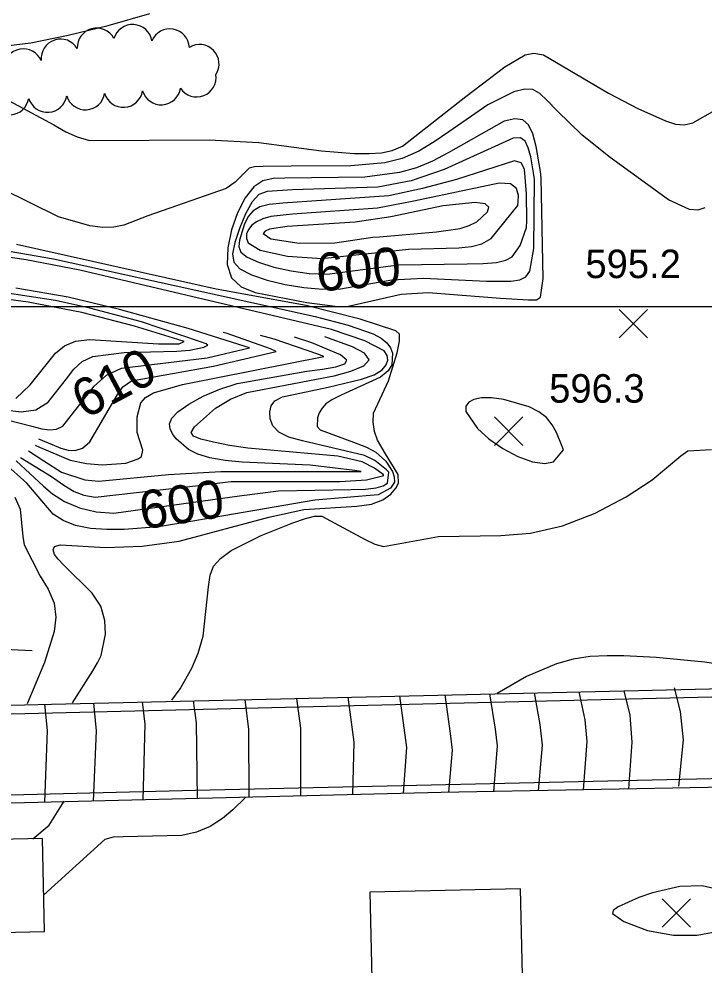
# Model space of a CAD drawing. Extents: x 79600 to 91800, y 75600 to 84400.
# Drawn here: x 88162.1 to 88522.6, y 78653.8 to 79151.4 of the extents above; entities that cross this region are included whole.
import ezdxf

# ---------------------------------------------------------------- set-up
doc = ezdxf.new("R2010")
doc.units = 0
for name, color, linetype in [('080-090$0$BLDG', 7, 'Continuous'), ('080-090$0$BRIDGE', 7, 'Continuous'), ('080-090$0$DRIVWY', 7, 'Continuous'), ('080-090$0$GRID', 7, 'Continuous'), ('080-090$0$INDEX', 7, 'Continuous'), ('080-090$0$INDXLBL', 7, 'Continuous'), ('080-090$0$INTER', 7, 'Continuous'), ('080-090$0$ROAD', 7, 'Continuous'), ('080-090$0$SPOTMARK', 7, 'Continuous'), ('080-090$0$SPOTS', 7, 'Continuous'), ('080-090$0$TREES', 7, 'Continuous')]:
    doc.layers.add(name, color=color, linetype=linetype)

# ---------------------------------------------------------------- blocks, each defined once
blk = doc.blocks.new('080-090$0$SPOTS')
at = {"layer": '080-090$0$SPOTMARK'}
for p, q in [((-0.5, -0.5), (0.5, 0.5)), ((-0.5, 0.5), (0.5, -0.5))]:
    blk.add_line(p, q, dxfattribs=at)

msp = doc.modelspace()

# ---------------------------------------------------------------- linework, layer by layer
at = {"layer": '080-090$0$BLDG'}
for points in [[(88098.7, 78669.76), (88175.62, 78671.53), (88174.5, 78720.41), (88097.58, 78718.64)], [(88346.79, 78692.15), (88354.12, 78373.51), (88433.35, 78375.34), (88426.02, 78693.98)]]:
    msp.add_lwpolyline(points, close=True, dxfattribs=at)
at = {"layer": '080-090$0$BRIDGE'}
for p, q in [((88179.19, 78791.07), (88533.01, 78799.31)), ((87904.96, 78784.84), (88179.19, 78791.07)), ((88825.9, 78753.07), (88384.29, 78744.54)), ((88384.29, 78744.54), (87934.81, 78733.66))]:
    msp.add_line(p, q, dxfattribs=at)
at = {"layer": '080-090$0$DRIVWY'}
msp.add_line((88131.98, 78821.14), (88169.06, 78819.2), dxfattribs=at)
at = {"layer": '080-090$0$GRID'}
msp.add_line((90000, 79000), (85000, 79000), dxfattribs=at)
at = {"layer": '080-090$0$INDEX'}
for points in [[(88429.23, 79045.27), (88429.2, 79059.44), (88428.16, 79072.45), (88426.37, 79075.74), (88422.83, 79076.74), (88392.28, 79067), (88374.37, 79062.17), (88356.66, 79058.27), (88300.88, 79054.58), (88293.83, 79053.79), (88288.77, 79052.51), (88285.3, 79050.54), (88282.82, 79047.62), (88280.81, 79043.69), (88278.19, 79035.08), (88277.83, 79031.61), (88278.88, 79028.7), (88282.13, 79026.04), (88288.13, 79023.39), (88296.18, 79020.92), (88305.34, 79018.91), (88314.79, 79017.6), (88324.3, 79017.11), (88361.82, 79022.12), (88397.96, 79022.59), (88406.34, 79022.71), (88413.28, 79023.27), (88418.22, 79024.45), (88421.57, 79026.31), (88425.86, 79032.18), (88429.18, 79041.68)], [(88528.32, 78693.96), (88521.58, 78695.48), (88509.88, 78695.15), (88495.38, 78691.78), (88488.28, 78689.33), (88477.36, 78684.43), (88474.73, 78682.6), (88474.32, 78680.96), (88480.33, 78676.77), (88492.71, 78672.04), (88506.4, 78669.6), (88518.98, 78669.58), (88529.21, 78671.43), (88536.38, 78674.68), (88538.7, 78676.63), (88540.1, 78678.72), (88540.44, 78681.01), (88537.33, 78686.56), (88529.83, 78693.45)]]:
    msp.add_lwpolyline(points, close=True, dxfattribs=at)
for points in [[(88160.67, 78919), (88175.05, 78905.62), (88179.7, 78901.62), (88186.08, 78897.69), (88193.94, 78894.33), (88202.77, 78892.13), (88212.09, 78891.5), (88279.42, 78900.85), (88298.67, 78903.19), (88336.86, 78903.94), (88344.43, 78904.15), (88350.02, 78904.81), (88353.78, 78905.89), (88356.02, 78907.3), (88356.72, 78913.08), (88355.5, 78914.29), (88349.36, 78919.11), (88343.91, 78921.84), (88311.37, 78929.55), (88304.18, 78931.46), (88298.78, 78933.99), (88295.63, 78937.34), (88294.31, 78941.12), (88294.18, 78944.81), (88294.83, 78947.96), (88296.77, 78950.56), (88300.76, 78952.7), (88324.84, 78957.8), (88342.37, 78961.9), (88348.94, 78964.28), (88353.16, 78966.83), (88355.37, 78969.43), (88356.16, 78971.97), (88355.9, 78974.37), (88354.17, 78976.76), (88344, 78982.15), (88326.57, 78988.06), (88222.38, 79012.53), (88194.15, 79019.26), (88165.83, 79024.73), (88146.62, 79027.59)], [(88135.26, 78945.74), (88168.84, 78937.21), (88174.22, 78935.77), (88178.39, 78935.25), (88181.9, 78935.72), (88185.22, 78937.28), (88201.71, 78958.21), (88208.15, 78964.08), (88216.12, 78967.74), (88261.13, 78973.18), (88283.38, 78978.34), (88280.66, 78979.34), (88251.17, 78988.63), (88214.96, 78998.5), (88187.92, 79005.01), (88160.5, 79009.79)], [(88480.35, 78798.08), (88483.45, 78785.18), (88484.59, 78771.1), (88482.76, 78746.44)], [(88362.33, 78795.34), (88366.05, 78768.29), (88364.3, 78744.05)], [(88226.95, 78792.18), (88228.3, 78780.44), (88227.31, 78740.74)]]:
    msp.add_lwpolyline(points, dxfattribs=at)
at = {"layer": '080-090$0$INTER'}
for points in [[(88142.81, 79115.89), (88180.37, 79095.72), (88186.72, 79092.08), (88192.78, 79089.3), (88199.26, 79087.52), (88262.16, 79087.89), (88288.35, 79086.47), (88321.21, 79082.02), (88338.51, 79080.67), (88346.3, 79080.54), (88352.78, 79080.93), (88358.42, 79082.15), (88363.9, 79084.54), (88397.21, 79110.63), (88417.79, 79126.28), (88428.35, 79132.44), (88432.96, 79133.39), (88438.05, 79132.5), (88472.22, 79112.38), (88487.66, 79104.32), (88502.29, 79097.74), (88507.61, 79096.01), (88512.09, 79095.65), (88516.7, 79096.81), (88528.35, 79103.45)], [(88522.87, 79052.03), (88519.29, 79050.83), (88514.96, 79051.14), (88503.77, 79056.17), (88473.19, 79078.43), (88458.35, 79090.24), (88445.2, 79103.12), (88440.08, 79108.48), (88436.11, 79112.25), (88432.49, 79114.26), (88428.19, 79114.49), (88422.48, 79112.97), (88408.78, 79106.22), (88388.25, 79091.96), (88380.63, 79086.71), (88372.42, 79081.85), (88363.68, 79078.04), (88354.54, 79075.7), (88336.78, 79074.08), (88305.37, 79073.91), (88290.59, 79073.83), (88286.06, 79073.6), (88283.16, 79072.88), (88275.86, 79065.47), (88271.17, 79062.23), (88229.95, 79047.92), (88217.21, 79043.01), (88211.99, 79041.8), (88206.28, 79041.63), (88199.33, 79042.58), (88182.96, 79047.33), (88031.53, 79121.93)], [(88190.35, 78791.8), (88200.89, 78808.62), (88203.42, 78812.73), (88205.36, 78816.7), (88207.62, 78827.79), (88207.3, 78835.07), (88205.11, 78842.53), (88200.68, 78849.45), (88185.49, 78864.39), (88182.67, 78867.35), (88180.89, 78869.83), (88180.06, 78872.11), (88180.82, 78873.92), (88183.99, 78874.86), (88207.67, 78873.44), (88226.97, 78874.13), (88246.46, 78876.71), (88293.58, 78889.36), (88312.05, 78893.38), (88339.8, 78895.18), (88347.52, 78896.25), (88353.5, 78898.51), (88357.74, 78901.53), (88360.42, 78904.65), (88361.72, 78907.33), (88361.59, 78911.81), (88354.92, 78922.62), (88350.77, 78929.87), (88349.14, 78934.49), (88348.4, 78939.31), (88348.58, 78944), (88356.58, 78961.12), (88361.16, 78975.73), (88362.34, 78981.95), (88362.24, 78985.55), (88360.41, 78987.37), (88341.56, 78993.45), (88313.24, 79000.65), (88265.78, 79009.23), (88160.83, 79032.77)], [(88152.9, 79029.95), (88180.36, 79025.29), (88291.82, 79000.77), (88317.97, 78994.94), (88335.31, 78990.32), (88348.41, 78985.72), (88352.63, 78983.47), (88355.59, 78981.07), (88357.52, 78978.43), (88358.57, 78975.58), (88358.29, 78969.5), (88356.35, 78966.33), (88352.33, 78963.05), (88331.6, 78953.51), (88326.74, 78951.11), (88323.62, 78948.98), (88321.59, 78946.76), (88320.14, 78944.22), (88319.17, 78941.57), (88318.94, 78937.09), (88320.51, 78935.28), (88338.03, 78928.76), (88344.93, 78926.2), (88349.85, 78923.63), (88355.11, 78918.88), (88358.57, 78913.45), (88359.52, 78910.53), (88359.69, 78907.79), (88357.64, 78904.71), (88351.08, 78901.12), (88317.69, 78898.34), (88253.52, 78887.34), (88235.58, 78884.33), (88217.41, 78882.9), (88208.35, 78882.86), (88199.7, 78883.5), (88191.94, 78885.05), (88185.42, 78887.66), (88180.16, 78891.04), (88166.29, 78907.28), (88154.48, 78917.7)], [(88154.48, 78945.82), (88163.24, 78944.83), (88171, 78945.9), (88177.44, 78949.92), (88187.1, 78962.06), (88191.03, 78967.29), (88195.33, 78971.26), (88200.94, 78973.95), (88217.51, 78976.02), (88245.14, 78976.66), (88252, 78977.16), (88259.44, 78978.75), (88261.53, 78979.9), (88260.68, 78980.46), (88257.66, 78981.62), (88226.66, 78992.07), (88199.48, 78999.28), (88181.36, 79003.25), (88153.62, 79007.53)], [(88160.46, 78951.85), (88168.06, 78959), (88181.29, 78975.64), (88186.04, 78979.52), (88191.94, 78981.95), (88199.48, 78982.8), (88235.61, 78980.56), (88246.48, 78980.48), (88248.98, 78981.83), (88245.78, 78982.86), (88222.88, 78989.86), (88195.2, 78996.99), (88167.03, 79002.39), (88148.71, 79004.95)], [(88338.89, 78913.86), (88315.39, 78916.73), (88279.54, 78918.25), (88270.53, 78919.12), (88262.56, 78920.52), (88256.2, 78922.55), (88251.32, 78925.03), (88244.82, 78930.49), (88242.84, 78933.21), (88241.67, 78935.89), (88241.37, 78938.53), (88242.5, 78941.39), (88245.73, 78944.76), (88251.46, 78948.78), (88259.1, 78952.99), (88267.82, 78956.77), (88276.88, 78959.65), (88313.58, 78966.08), (88321.82, 78967.27), (88328.88, 78968.49), (88333.6, 78969.98), (88334.67, 78972), (88331.26, 78974.73), (88316.16, 78981.1), (88307.01, 78983.95)], [(88353.73, 78911.73), (88349.2, 78915.16), (88342.61, 78918.53), (88329.87, 78921.38), (88282.46, 78925.68), (88272.96, 78927.12), (88264.46, 78928.79), (88257.84, 78930.42), (88253.86, 78931.93), (88252.71, 78933.84), (88254.44, 78936.87), (88265.55, 78946.62), (88273.47, 78951.4), (88282.01, 78954.9), (88318.71, 78961.96), (88327.96, 78963.78), (88336.74, 78966.14), (88343.47, 78968.97), (88346.28, 78972.16), (88343.93, 78975.55), (88337.64, 78978.96), (88322.95, 78984.17)], [(88294.39, 78977.81), (88271.7, 78985.9), (88269.5, 78986.53)], [(88319.39, 78975.09), (88296.41, 78982.91), (88289.2, 78984.87)], [(88172.46, 78930.51), (88179.56, 78927.63), (88184.09, 78925.74), (88188, 78924.64), (88191.73, 78924.48), (88195.49, 78925.72), (88199.43, 78928.94), (88213.85, 78953.49), (88216.81, 78957.87), (88221.25, 78961.06), (88264.47, 78968.7), (88297.39, 78976.58), (88294.39, 78977.81)], [(88170.56, 78927.2), (88172.85, 78926.11), (88189.13, 78919.41), (88197.73, 78917.61), (88205.88, 78916.92), (88218.31, 78917.76), (88224.88, 78920), (88226.58, 78921.23), (88227.31, 78924.54), (88224.38, 78933.86), (88224.31, 78942.1), (88226.27, 78949.43), (88228.63, 78952.34), (88232.92, 78954.84), (88248.17, 78959.1), (88322.58, 78973.92), (88319.39, 78975.09)], [(88167.1, 78924.24), (88175.24, 78919.01), (88184.53, 78913.07), (88196.68, 78909.04), (88204.21, 78908.29), (88240.77, 78911.87), (88268.35, 78913.38), (88342.09, 78913.36), (88338.89, 78913.86)], [(88242.47, 78793.21), (88246.94, 78799.11), (88253, 78810.03), (88256.33, 78817.89), (88259, 78826.75), (88261.83, 78852.81), (88262.68, 78858.84), (88264.53, 78863.58), (88268.06, 78867.71), (88273.73, 78871.81), (88289.47, 78879.78), (88306.25, 78886.38), (88312.9, 78888.63), (88317.6, 78889.88), (88321.38, 78889.85), (88344.22, 78877.58), (88349.3, 78875.11), (88353.98, 78873.98), (88382.78, 78879.14), (88415.58, 78879.73), (88431.27, 78880.93), (88448.03, 78884.84), (88465.28, 78891.55), (88481.56, 78900.07), (88495.32, 78908.94), (88510.32, 78921.71), (88514.07, 78924.22), (88526.48, 78924.88)], [(88162.93, 78920.73), (88179.22, 78910.69), (88185.69, 78906.23), (88191.12, 78902.94), (88196.31, 78900.88), (88202.27, 78899.94), (88255.06, 78905.77), (88273.51, 78908.05), (88331, 78908.18), (88344.94, 78908.94), (88354.16, 78911.28), (88353.73, 78911.73)], [(88159.91, 78899.91), (88162.66, 78893.57), (88164.23, 78879.27), (88164.91, 78874.91), (88173.35, 78858.42), (88177.52, 78851.47), (88180.56, 78844.21), (88181.5, 78836.86), (88180.6, 78829.31), (88175.57, 78812.88), (88166.38, 78791.15)], [(88582.78, 78800), (88564.13, 78805.54), (88547.6, 78809.28), (88522.89, 78813.06), (88497.35, 78815.5), (88480.3, 78816.38), (88471.55, 78816.53), (88462.66, 78816.12), (88453.71, 78814.78), (88444.83, 78812.26), (88429.13, 78805.52), (88413.76, 78796.69)], [(88506.79, 78799.6), (88509.98, 78787.24), (88511.49, 78772.31), (88509.14, 78747.85)], [(88280.94, 78793.44), (88282.93, 78777.75), (88283.06, 78742.09)], [(88308.07, 78794.07), (88310.15, 78778.5), (88310.3, 78742.75)], [(88335.2, 78794.7), (88338.24, 78771.08), (88337.53, 78743.41)], [(88386.25, 78795.89), (88389.04, 78775.55), (88390.09, 78766.92), (88388.13, 78744.61)], [(88409.71, 78796.44), (88412.64, 78777.96), (88413.62, 78769.15), (88411.71, 78745.07)], [(88433.21, 78796.99), (88436.23, 78780.37), (88437.3, 78769.52), (88435.29, 78745.52)], [(88456.75, 78797.53), (88459.84, 78782.78), (88460.85, 78771.41), (88458.88, 78745.98)], [(88175.54, 78790.99), (88176.95, 78777.23), (88175.49, 78739.48)], [(88201.35, 78791.59), (88202.78, 78777.1), (88201.17, 78740.11)], [(88253.81, 78792.81), (88255.41, 78781.23), (88255.82, 78741.43)], [(88169.43, 78720.29), (88177.92, 78727.49), (88185.98, 78740.06)], [(88281.46, 78742.08), (88274.66, 78735.4), (88269.27, 78730.86), (88262.78, 78726.66), (88255.55, 78723.73), (88247.8, 78722.01), (88216.92, 78721.34), (88211.69, 78721.05), (88207.28, 78719.79), (88175.18, 78690.8)]]:
    msp.add_lwpolyline(points, dxfattribs=at)
for points in [[(88436.44, 79071.19), (88434.2, 79084.25), (88432.43, 79090.96), (88430.18, 79095.71), (88427.13, 79098.31), (88422.94, 79098.86), (88417.37, 79097.54), (88387.92, 79081.01), (88379.74, 79076.58), (88371.21, 79073.13), (88362.38, 79070.65), (88344.03, 79068.16), (88302.02, 79067.69), (88295.85, 79067.45), (88290.47, 79066.22), (88285.62, 79063.04), (88281.13, 79057.26), (88277.16, 79049.44), (88273.99, 79040.41), (88271.93, 79031.04), (88271.65, 79022.31), (88273.86, 79015.21), (88279.01, 79010.43), (88286.46, 79007.46), (88313.54, 79002.26), (88328.46, 79000.31), (88334.57, 79000.18), (88355.56, 79004.88), (88363.18, 79006.65), (88377.38, 79007.44), (88415.45, 79004.61), (88430.25, 79003.63), (88434.36, 79003.68), (88436.47, 79004.99), (88437.88, 79014.82), (88436.92, 79067.85)], [(88432.95, 79069.33), (88431.33, 79078.81), (88430.05, 79083.67), (88428.37, 79087.09), (88425.9, 79088.79), (88422.14, 79088.69), (88385.84, 79072.27), (88368.47, 79066.29), (88350.94, 79062.89), (88305.95, 79061.45), (88292.66, 79060.71), (88288.36, 79059.04), (88284.74, 79055.28), (88281.24, 79048.92), (88278.09, 79041.19), (88275.69, 79033.76), (88274.47, 79027.92), (88275.09, 79023.5), (88278.27, 79019.93), (88284.39, 79016.79), (88292.72, 79014.04), (88302.22, 79011.79), (88311.98, 79010.14), (88321.73, 79009.3), (88331.31, 79009.48), (88358.27, 79014.12), (88374.93, 79015.1), (88408.02, 79013.48), (88420.97, 79013.48), (88425.6, 79014.24), (88428.8, 79015.8), (88430.87, 79018.72), (88433, 79030.67), (88433.3, 79066.87)], [(88424.78, 79055.31), (88424.84, 79058.55), (88423.89, 79062.13), (88420.77, 79064.66), (88414.73, 79065.09), (88369.83, 79055.55), (88350.81, 79051.9), (88305.99, 79048.76), (88294.6, 79047.47), (88290.38, 79046.31), (88287.06, 79044.77), (88284.55, 79042.88), (88282.82, 79040.68), (88281.89, 79038.31), (88281.78, 79035.93), (88282.62, 79033.69), (88288.97, 79029.7), (88303.38, 79026.58), (88321.43, 79025.39), (88366.98, 79030.27), (88393.51, 79031.09), (88400.11, 79031.66), (88405.59, 79033.11), (88410.47, 79035.94), (88424.55, 79053.35)], [(88351.8, 79036.88), (88381.79, 79039.48), (88394.19, 79041.17), (88399.01, 79042.69), (88402.99, 79044.7), (88408.63, 79049.87), (88409.37, 79052.4), (88407.41, 79054.19), (88402.12, 79054.82), (88385.35, 79053.13), (88357.68, 79047.32), (88339.05, 79044.55), (88303.28, 79042.19), (88293.99, 79040.77), (88291.71, 79039.76), (88290.65, 79038.55), (88294.71, 79035.81), (88309.56, 79033.51), (88328.31, 79033.7), (88348.27, 79036.54)], [(88447.98, 78926.56), (88445, 78933.82), (88442.62, 78938.01), (88439.6, 78941.7), (88435.7, 78944.82), (88430.59, 78947.46), (88417.26, 78951.28), (88410.75, 78952.15), (88405.45, 78952.14), (88401.46, 78951.33), (88398.72, 78949.85), (88397.22, 78947.75), (88397.27, 78944.88), (88403.39, 78936.02), (88409.35, 78930.57), (88416.6, 78925.41), (88424.57, 78921.25), (88432.33, 78918.51), (88438.86, 78917.54), (88443.4, 78918.48), (88448.57, 78924.76)]]:
    msp.add_lwpolyline(points, close=True, dxfattribs=at)
at = {"layer": '080-090$0$ROAD'}
for p, q in [((88208.97, 79147.96), (88231.03, 79154.31)), ((88188.07, 79142.84), (88208.97, 79147.96)), ((88168.3, 79138.81), (88188.07, 79142.84)), ((88146.33, 79136.09), (88168.3, 79138.81)), ((88839.1, 78801.07), (88504.57, 78794.22)), ((88504.57, 78794.22), (88113.04, 78784.71)), ((88254.95, 78745.86), (88573.44, 78752.92)), ((87988.1, 78739.04), (88254.95, 78745.86))]:
    msp.add_line(p, q, dxfattribs=at)
at = {"layer": '080-090$0$TREES'}
for centre, start, end in [((88203.04, 79136.29), 28.0093, 182.6486), ((88221.92, 79138.21), 8.9651, 163.6043), ((88241.52, 79135.9), 2.9211, 157.5604), ((88184.03, 79130.52), 31.1417, 185.7809), ((88257.14, 79127.69), 327.0293, 121.6685), ((88164.41, 79125.44), 23.2398, 177.879), ((88255.6, 79120.6), 213.8657, 8.505), ((88197.05, 79113.84), 196.4527, 351.092), ((88217.01, 79115.16), 196.4527, 351.092), ((88236.97, 79116.48), 196.4527, 351.092), ((88157.14, 79111.21), 196.4527, 351.092), ((88177.1, 79112.53), 196.4527, 351.092)]:
    msp.add_arc(centre, 10.25, start, end, dxfattribs=at)

# ---------------------------------------------------------------- block references
at = {"layer": '080-090$0$SPOTMARK', "xscale": 15, "yscale": 15}
for p in [(88485.32, 78991.13), (88419.72, 78934.58), (88507.95, 78681.22)]:
    msp.add_blockref('080-090$0$SPOTS', p, dxfattribs=at)

# ---------------------------------------------------------------- texts
at = {"layer": '080-090$0$INDXLBL'}
for s, rotation, p in [('600', 4.8023, (88319.24, 79007.99)), ('610', 28.0098, (88196.85, 78940.76)), ('600', 9.0451, (88227.07, 78882.78))]:
    msp.add_text(s, height=20, rotation=rotation, dxfattribs=at).set_placement(p)
at = {"layer": '080-090$0$SPOTS'}
for s, p in [('595.2', (88460.14, 79015.08)), ('596.3', (88441.07, 78949.58))]:
    msp.add_text(s, height=15, dxfattribs=at).set_placement(p)

doc.saveas('drawing.dxf')
